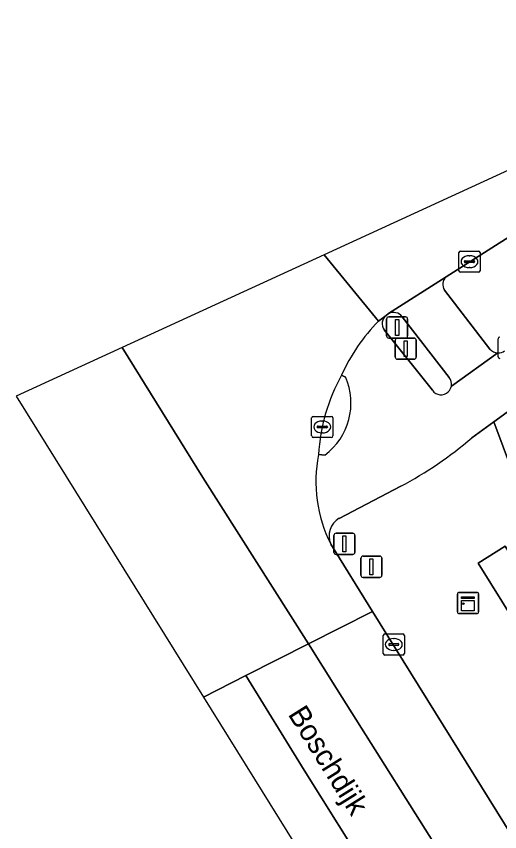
# Model space of a CAD drawing. Extents: x 160806 to 161707, y 383696 to 384148.
# Drawn here: x 160892.89 to 160915.71, y 383917.51 to 383955.96 of the extents above; entities that cross this region are included whole.
import ezdxf

# ---------------------------------------------------------------- set-up
doc = ezdxf.new("R2010")
doc.units = 0
for name, color, linetype in [('IMGEO_Drukknoppaal', 7, 'Continuous'), ('IMGEO_Fietspad_open', 7, 'Continuous'), ('IMGEO_Groenvoorziening', 7, 'Continuous'), ('IMGEO_Haag', 7, 'Continuous'), ('IMGEO_Kast', 7, 'Continuous'), ('IMGEO_Kolk', 7, 'Continuous'), ('IMGEO_Lichtmast', 7, 'Continuous'), ('IMGEO_Openbare_ruimte_label', 7, 'Continuous'), ('IMGEO_Rijbaan_lokaal_gesloten', 7, 'Continuous'), ('IMGEO_Rijbaan_lokaal_open', 7, 'Continuous'), ('IMGEO_Verkeerseiland_gesloten', 7, 'Continuous'), ('IMGEO_Verkeerseiland_groen', 7, 'Continuous'), ('IMGEO_Verkeerseiland_open', 7, 'Continuous'), ('IMGEO_Verkeersregelinstallatiepaal', 7, 'Continuous'), ('IMGEO_Voetpad_open', 7, 'Continuous')]:
    doc.layers.add(name, color=color, linetype=linetype)

msp = doc.modelspace()

# ---------------------------------------------------------------- linework, layer by layer
at = {"layer": 'IMGEO_Drukknoppaal'}
for p, q in [((160910.376, 383940.887), (160910.376, 383941.687)), ((160910.376, 383941.687), (160910.376, 383940.887)), ((160910.476, 383941.787), (160911.266, 383941.787)), ((160911.266, 383941.787), (160910.476, 383941.787)), ((160911.366, 383941.687), (160911.366, 383940.887)), ((160911.366, 383940.887), (160911.366, 383941.687)), ((160911.266, 383940.787), (160910.476, 383940.787)), ((160910.476, 383940.787), (160911.266, 383940.787))]:
    msp.add_line(p, q, dxfattribs=at)
msp.add_lwpolyline([(160910.796, 383941.662), (160910.946, 383941.662), (160910.946, 383940.912), (160910.796, 383940.912), (160910.796, 383941.662)], dxfattribs=at)
for centre, start, end in [((160910.476, 383941.687), 90, 180), ((160910.476, 383941.687), 90, 180), ((160911.266, 383941.687), 0, 90), ((160911.266, 383941.687), 360, 90), ((160910.476, 383940.887), 180, 270), ((160910.476, 383940.887), 180, 270), ((160911.266, 383940.887), 270, 0), ((160911.266, 383940.887), 270, 0)]:
    msp.add_arc(centre, 0.1, start, end, dxfattribs=at)
at = {"layer": 'IMGEO_Fietspad_open'}
for points in [[(160914.394, 383936.084), (160915.435, 383936.839), (160928.691, 383946.466), (160930.868, 383948.143)], [(160910.348, 383941.857), (160909.99, 383941.586)], [(160912.535, 383938.326), (160910.264, 383941.18)], [(160915.627, 383940.088), (160913.432, 383938.517)], [(160908.246, 383939.039), (160908.436, 383938.952)], [(160907.466, 383935.27), (160907.157, 383935.291)], [(160908.137, 383932.288), (160911.047, 383933.797)]]:
    msp.add_lwpolyline(points, dxfattribs=at)
for centre, radius, start, end in [((160910.656, 383941.475), 0.491, 128.8757, 216.9784), ((160916.234, 383935.44), 8.761, 135.4529, 155.7461), ((160915.641, 383940.616), 0.528, 268.4309, 304.9344), ((160905.618, 383937.726), 3.073, 306.9626, 23.5196), ((160912.945, 383938.61), 0.495, 313.4444, 349.2145), ((160912.943, 383938.609), 0.497, 214.7488, 313.6941), ((160902.215, 383950.316), 18.732, 298.1328, 310.5567), ((160913.674, 383934.037), 6.637, 169.108, 206.5048), ((160908.632, 383931.451), 0.973, 120.6113, 202.7173)]:
    msp.add_arc(centre, radius, start, end, dxfattribs=at)
at = {"layer": 'IMGEO_Groenvoorziening'}
msp.add_lwpolyline([(160916.408, 383927.422), (160917.684, 383928.212), (160915.977, 383930.968), (160914.701, 383930.178)], close=True, dxfattribs=at)
at = {"layer": 'IMGEO_Haag'}
msp.add_lwpolyline([(160916.408, 383927.422), (160917.684, 383928.212), (160915.977, 383930.968), (160914.701, 383930.178)], close=True, dxfattribs=at)
at = {"layer": 'IMGEO_Kast'}
for p, q in [((160913.79, 383928.797), (160914.631, 383928.797)), ((160914.631, 383928.797), (160913.79, 383928.797)), ((160914.715, 383928.722), (160914.715, 383927.881)), ((160914.715, 383927.881), (160914.715, 383928.722)), ((160913.715, 383927.872), (160913.715, 383928.713)), ((160913.715, 383928.713), (160913.715, 383927.872)), ((160914.64, 383927.797), (160913.799, 383927.797)), ((160913.799, 383927.797), (160914.64, 383927.797))]:
    msp.add_line(p, q, dxfattribs=at)
for points in [[(160913.91, 383928.587), (160914.51, 383928.587), (160914.51, 383928.502), (160913.91, 383928.502), (160913.91, 383928.587)], [(160913.91, 383928.412), (160914.51, 383928.412), (160914.51, 383927.923), (160913.91, 383927.923), (160913.91, 383928.412)]]:
    msp.add_lwpolyline(points, dxfattribs=at)
msp.add_circle((160913.994, 383928.261), 0.0377, dxfattribs=at)
for centre, start, end in [((160913.793, 383928.719), 92.4484, 184.2845), ((160913.793, 383928.719), 92.4484, 184.2845), ((160914.637, 383928.719), 2.4484, 94.2845), ((160914.637, 383928.719), 2.4484, 94.2845), ((160913.793, 383927.875), 182.4484, 274.2845), ((160913.793, 383927.875), 182.4484, 274.2845), ((160914.637, 383927.875), 272.4484, 4.2845), ((160914.637, 383927.875), 272.4484, 4.2845)]:
    msp.add_arc(centre, 0.0779, start, end, dxfattribs=at)
at = {"layer": 'IMGEO_Kolk'}
for p, q in [((160913.86, 383944.892), (160914.712, 383944.892)), ((160913.785, 383943.966), (160913.785, 383944.818)), ((160914.273, 383944.672), (160914.298, 383944.672)), ((160914.786, 383944.818), (160914.786, 383943.966)), ((160914.044, 383944.386), (160914.044, 383944.398)), ((160914.482, 383944.349), (160914.084, 383944.349)), ((160914.087, 383944.435), (160914.485, 383944.435)), ((160914.296, 383944.112), (160914.271, 383944.112)), ((160914.528, 383944.398), (160914.528, 383944.386)), ((160914.712, 383943.892), (160913.86, 383943.892)), ((160915.637, 383939.904), (160915.637, 383940.756)), ((160906.836, 383936.171), (160906.836, 383937.023)), ((160906.911, 383937.097), (160907.763, 383937.097)), ((160907.324, 383936.877), (160907.349, 383936.877)), ((160907.837, 383937.023), (160907.837, 383936.171)), ((160907.095, 383936.591), (160907.095, 383936.603)), ((160907.533, 383936.554), (160907.135, 383936.554)), ((160907.138, 383936.64), (160907.536, 383936.64)), ((160907.579, 383936.603), (160907.579, 383936.591)), ((160907.763, 383936.097), (160906.911, 383936.097)), ((160907.347, 383936.317), (160907.322, 383936.317)), ((160910.287, 383926.84), (160911.139, 383926.84)), ((160910.212, 383925.914), (160910.212, 383926.766)), ((160910.7, 383926.62), (160910.725, 383926.62)), ((160911.213, 383926.766), (160911.213, 383925.914)), ((160910.471, 383926.334), (160910.471, 383926.346)), ((160910.909, 383926.297), (160910.511, 383926.297)), ((160910.514, 383926.383), (160910.912, 383926.383)), ((160910.723, 383926.06), (160910.698, 383926.06)), ((160910.955, 383926.346), (160910.955, 383926.334)), ((160911.139, 383925.84), (160910.287, 383925.84))]:
    msp.add_line(p, q, dxfattribs=at)
for points in [[(160913.86, 383944.892), (160914.712, 383944.892)], [(160913.785, 383943.966), (160913.785, 383944.818)], [(160914.786, 383944.818), (160914.786, 383943.966)], [(160914.712, 383943.892), (160913.86, 383943.892)], [(160915.637, 383939.904), (160915.637, 383940.756)], [(160906.836, 383936.171), (160906.836, 383937.023)], [(160906.911, 383937.097), (160907.763, 383937.097)], [(160907.837, 383937.023), (160907.837, 383936.171)], [(160907.763, 383936.097), (160906.911, 383936.097)], [(160910.287, 383926.84), (160911.139, 383926.84)], [(160910.212, 383925.914), (160910.212, 383926.766)], [(160911.213, 383926.766), (160911.213, 383925.914)], [(160911.139, 383925.84), (160910.287, 383925.84)]]:
    msp.add_lwpolyline(points, dxfattribs=at)
for centre, radius, start, end in [((160913.862, 383944.816), 0.0765, 91.552, 178.448), ((160913.862, 383944.816), 0.0765, 91.552, 178.448), ((160914.71, 383944.816), 0.0765, 1.552, 88.448), ((160914.71, 383944.816), 0.0765, 1.552, 88.448), ((160914.084, 383944.395), 0.0403, 85.8775, 175.7526), ((160914.081, 383944.385), 0.0366, 178.938, 274.7102), ((160914.485, 383944.392), 0.043, 264.8664, 352.4533), ((160914.489, 383944.397), 0.0386, 1.7309, 96.639), ((160913.862, 383943.968), 0.0765, 181.552, 268.448), ((160913.862, 383943.968), 0.0765, 181.552, 268.448), ((160914.71, 383943.968), 0.0765, 271.552, 358.448), ((160914.71, 383943.968), 0.0765, 271.552, 358.448), ((160915.714, 383940.754), 0.0765, 91.552, 178.448), ((160915.714, 383940.754), 0.0765, 91.552, 178.448), ((160915.714, 383939.906), 0.0765, 181.552, 268.448), ((160915.714, 383939.906), 0.0765, 181.552, 268.448), ((160906.913, 383937.021), 0.0765, 91.552, 178.448), ((160906.913, 383937.021), 0.0765, 91.552, 178.448), ((160907.761, 383937.021), 0.0765, 1.552, 88.448), ((160907.761, 383937.021), 0.0765, 1.552, 88.448), ((160907.135, 383936.6), 0.0403, 85.8775, 175.7526), ((160907.132, 383936.59), 0.0366, 178.938, 274.7102), ((160907.536, 383936.597), 0.043, 264.8664, 352.4533), ((160907.54, 383936.602), 0.0386, 1.7309, 96.639), ((160906.913, 383936.173), 0.0765, 181.552, 268.448), ((160906.913, 383936.173), 0.0765, 181.552, 268.448), ((160907.761, 383936.173), 0.0765, 271.552, 358.448), ((160907.761, 383936.173), 0.0765, 271.552, 358.448), ((160910.289, 383926.764), 0.0765, 91.552, 178.448), ((160910.289, 383926.764), 0.0765, 91.552, 178.448), ((160911.137, 383926.764), 0.0765, 1.552, 88.448), ((160911.137, 383926.764), 0.0765, 1.552, 88.448), ((160910.511, 383926.343), 0.0403, 85.8775, 175.7526), ((160910.508, 383926.333), 0.0366, 178.938, 274.7102), ((160910.912, 383926.34), 0.043, 264.8664, 352.4533), ((160910.916, 383926.345), 0.0386, 1.7309, 96.639), ((160910.289, 383925.916), 0.0765, 181.552, 268.448), ((160910.289, 383925.916), 0.0765, 181.552, 268.448), ((160911.137, 383925.916), 0.0765, 271.552, 358.448), ((160911.137, 383925.916), 0.0765, 271.552, 358.448)]:
    msp.add_arc(centre, radius, start, end, dxfattribs=at)
for centre, major_axis, ratio, start_param, end_param in [((160914.272, 383944.392), (-0.387, 0.002), 0.722429, 4.712389, 7.853982), ((160914.297, 383944.392), (-0.39, 0.002), 0.717154, 1.570796, 4.712389), ((160907.323, 383936.597), (-0.387, 0.002), 0.722429, 4.712389, 7.853982), ((160907.348, 383936.597), (-0.39, 0.002), 0.717154, 1.570796, 4.712389), ((160910.699, 383926.34), (-0.387, 0.002), 0.722429, 4.712389, 7.853982), ((160910.724, 383926.34), (-0.39, 0.002), 0.717154, 1.570796, 4.712389)]:
    msp.add_ellipse(centre, major_axis=major_axis, ratio=ratio, start_param=start_param, end_param=end_param, dxfattribs=at)
at = {"layer": 'IMGEO_Lichtmast'}
for p, q in [((160907.885, 383930.684), (160907.885, 383931.484)), ((160907.885, 383931.484), (160907.885, 383930.684)), ((160907.985, 383931.584), (160908.775, 383931.584)), ((160908.775, 383931.584), (160907.985, 383931.584)), ((160908.875, 383931.484), (160908.875, 383930.684)), ((160908.875, 383930.684), (160908.875, 383931.484)), ((160908.775, 383930.584), (160907.985, 383930.584)), ((160907.985, 383930.584), (160908.775, 383930.584))]:
    msp.add_line(p, q, dxfattribs=at)
msp.add_lwpolyline([(160908.305, 383931.459), (160908.455, 383931.459), (160908.455, 383930.709), (160908.305, 383930.709), (160908.305, 383931.459)], dxfattribs=at)
for centre, start, end in [((160907.985, 383931.484), 90, 180), ((160907.985, 383931.484), 90, 180), ((160908.775, 383931.484), 0, 90), ((160908.775, 383931.484), 360, 90), ((160907.985, 383930.684), 180, 270), ((160907.985, 383930.684), 180, 270), ((160908.775, 383930.684), 270, 0), ((160908.775, 383930.684), 270, 0)]:
    msp.add_arc(centre, 0.1, start, end, dxfattribs=at)
at = {"layer": 'IMGEO_Rijbaan_lokaal_gesloten'}
for points in [[(160909.99, 383941.586), (160907.425, 383944.713), (160897.886, 383940.336)], [(160897.886, 383940.336), (160892.895, 383938.045), (160901.725, 383923.859), (160903.723, 383924.87), (160906.682, 383926.368), (160901.707, 383934.21), (160897.886, 383940.336)], [(160897.886, 383940.336), (160901.707, 383934.21), (160906.682, 383926.368), (160909.71, 383927.9), (160907.735, 383931.075)], [(160909.71, 383927.9), (160906.682, 383926.368), (160908.015, 383924.267), (160913.566, 383915.455), (160925.814, 383895.944), (160938.564, 383875.623), (160945.002, 383865.641)], [(160936.803, 383883.721), (160935.997, 383885.302), (160935.062, 383887.143), (160909.71, 383927.9)], [(160949.144, 383858.905), (160948.516, 383859.997), (160945.002, 383865.641), (160938.564, 383875.623), (160925.814, 383895.944), (160913.566, 383915.455), (160908.015, 383924.267), (160906.682, 383926.368), (160903.723, 383924.87), (160906.479, 383920.419), (160912.866, 383910.221), (160927.745, 383886.505), (160950.252, 383850.619), (160952.745, 383846.411), (160954.11, 383843.892), (160955.019, 383841.251), (160955.876, 383837.546), (160955.934, 383835.901), (160961.513, 383837.987), (160963.214, 383838.795)], [(160954.311, 383835.295), (160955.934, 383835.901), (160955.876, 383837.546), (160955.019, 383841.251), (160954.11, 383843.892), (160952.745, 383846.411), (160950.252, 383850.619), (160927.745, 383886.505), (160912.866, 383910.221), (160906.479, 383920.419), (160903.723, 383924.87), (160901.725, 383923.859), (160952.654, 383842.04), (160954.311, 383835.295)]]:
    msp.add_lwpolyline(points, dxfattribs=at)
for centre, radius, start, end in [((160916.234, 383935.44), 8.761, 135.4529, 155.7461), ((160916.102, 383934.724), 8.963, 151.2222, 176.3749), ((160913.674, 383934.037), 6.637, 169.108, 206.5048)]:
    msp.add_arc(centre, radius, start, end, dxfattribs=at)
at = {"layer": 'IMGEO_Rijbaan_lokaal_open'}
for points in [[(161008.487, 383991.097), (160907.425, 383944.713)], [(160907.425, 383944.713), (160909.99, 383941.586), (160910.348, 383941.857), (160910.466, 383941.945), (160913.178, 383943.681), (160916.333, 383945.674), (160930.784, 383954.763), (160931.961, 383955.496), (160937.776, 383958.172), (160945.199, 383961.672), (160948.108, 383963.03), (160966.644, 383971.527)]]:
    msp.add_lwpolyline(points, dxfattribs=at)
at = {"layer": 'IMGEO_Verkeerseiland_gesloten'}
for points in [[(160910.466, 383941.945), (160910.348, 383941.857)], [(160913.323, 383938.932), (160911.109, 383941.796)], [(160910.264, 383941.18), (160912.535, 383938.326)]]:
    msp.add_lwpolyline(points, dxfattribs=at)
for centre, radius, start, end in [((160910.656, 383941.475), 0.491, 128.8757, 216.9784), ((160910.694, 383941.468), 0.529, 38.351, 115.5556), ((160912.948, 383938.612), 0.493, 348.9258, 40.507), ((160912.945, 383938.61), 0.495, 313.4444, 349.2145), ((160912.943, 383938.609), 0.497, 214.7488, 313.6941)]:
    msp.add_arc(centre, radius, start, end, dxfattribs=at)
at = {"layer": 'IMGEO_Verkeerseiland_groen'}
for points in [[(160916.333, 383945.674), (160913.178, 383943.681)], [(160913.107, 383943.045), (160915.249, 383940.272)]]:
    msp.add_lwpolyline(points, dxfattribs=at)
for centre, radius, start, end in [((160913.527, 383943.32), 0.502, 134.0183, 213.242), ((160915.647, 383940.609), 0.521, 220.2524, 267.8365), ((160915.641, 383940.616), 0.528, 268.4309, 304.9344)]:
    msp.add_arc(centre, radius, start, end, dxfattribs=at)
at = {"layer": 'IMGEO_Verkeerseiland_open'}
for points in [[(160908.436, 383938.952), (160908.246, 383939.039)], [(160907.157, 383935.291), (160907.466, 383935.27)]]:
    msp.add_lwpolyline(points, dxfattribs=at)
for centre, radius, start, end in [((160916.102, 383934.724), 8.963, 151.2222, 176.3749), ((160905.618, 383937.726), 3.073, 306.9626, 23.5196)]:
    msp.add_arc(centre, radius, start, end, dxfattribs=at)
at = {"layer": 'IMGEO_Verkeersregelinstallatiepaal'}
for p, q in [((160910.781, 383939.889), (160910.781, 383940.689)), ((160910.781, 383940.689), (160910.781, 383939.889)), ((160910.881, 383940.789), (160911.671, 383940.789)), ((160911.671, 383940.789), (160910.881, 383940.789)), ((160911.771, 383940.689), (160911.771, 383939.889)), ((160911.771, 383939.889), (160911.771, 383940.689)), ((160911.671, 383939.789), (160910.881, 383939.789)), ((160910.881, 383939.789), (160911.671, 383939.789)), ((160909.161, 383929.605), (160909.161, 383930.405)), ((160909.161, 383930.405), (160909.161, 383929.605)), ((160909.261, 383930.505), (160910.051, 383930.505)), ((160910.051, 383930.505), (160909.261, 383930.505)), ((160910.151, 383930.405), (160910.151, 383929.605)), ((160910.151, 383929.605), (160910.151, 383930.405)), ((160910.051, 383929.505), (160909.261, 383929.505)), ((160909.261, 383929.505), (160910.051, 383929.505))]:
    msp.add_line(p, q, dxfattribs=at)
for points in [[(160911.201, 383940.664), (160911.351, 383940.664), (160911.351, 383939.914), (160911.201, 383939.914), (160911.201, 383940.664)], [(160909.581, 383930.38), (160909.731, 383930.38), (160909.731, 383929.63), (160909.581, 383929.63), (160909.581, 383930.38)]]:
    msp.add_lwpolyline(points, dxfattribs=at)
for centre, start, end in [((160910.881, 383940.689), 90, 180), ((160910.881, 383940.689), 90, 180), ((160911.671, 383940.689), 0, 90), ((160911.671, 383940.689), 360, 90), ((160910.881, 383939.889), 180, 270), ((160910.881, 383939.889), 180, 270), ((160911.671, 383939.889), 270, 0), ((160911.671, 383939.889), 270, 0), ((160909.261, 383930.405), 90, 180), ((160909.261, 383930.405), 90, 180), ((160910.051, 383930.405), 0, 90), ((160910.051, 383930.405), 360, 90), ((160909.261, 383929.605), 180, 270), ((160909.261, 383929.605), 180, 270), ((160910.051, 383929.605), 270, 0), ((160910.051, 383929.605), 270, 0)]:
    msp.add_arc(centre, 0.1, start, end, dxfattribs=at)
at = {"layer": 'IMGEO_Voetpad_open'}
for points in [[(160930.868, 383948.143), (160928.691, 383946.466), (160915.435, 383936.839), (160917.241, 383931.994), (160917.656, 383932.175), (160917.798, 383931.792), (160919.628, 383932.473), (160919.501, 383932.83), (160920.227, 383933.101), (160919.857, 383934.55), (160919.885, 383935.916), (160932.177, 383945.058), (160934.167, 383946.323), (160938.381, 383949.591), (160940.209, 383950.755), (160941.963, 383951.859), (160947.428, 383954.476), (160947.637, 383954.018), (160948.491, 383954.34), (160961.285, 383959.048), (160961.058, 383959.607), (160959.525, 383959.063)], [(160913.178, 383943.681), (160910.466, 383941.945)], [(160915.249, 383940.272), (160913.107, 383943.045)], [(160911.109, 383941.796), (160913.323, 383938.932)], [(160913.432, 383938.517), (160915.627, 383940.088)], [(160917.241, 383931.994), (160915.435, 383936.839), (160914.394, 383936.084)], [(160911.047, 383933.797), (160908.137, 383932.288)], [(160907.735, 383931.075), (160909.71, 383927.9), (160935.062, 383887.143), (160935.997, 383885.302), (160936.803, 383883.721)]]:
    msp.add_lwpolyline(points, dxfattribs=at)
msp.add_lwpolyline([(160914.701, 383930.178), (160915.977, 383930.968), (160917.684, 383928.212), (160916.408, 383927.422)], close=True, dxfattribs=at)
for centre, radius, start, end in [((160913.527, 383943.32), 0.502, 134.0183, 213.242), ((160910.694, 383941.468), 0.529, 38.351, 115.5556), ((160915.647, 383940.609), 0.521, 220.2524, 267.8365), ((160912.948, 383938.612), 0.493, 348.9258, 40.507), ((160902.215, 383950.316), 18.732, 298.1328, 310.5567), ((160908.632, 383931.451), 0.973, 120.6113, 202.7173)]:
    msp.add_arc(centre, radius, start, end, dxfattribs=at)

# ---------------------------------------------------------------- texts
at = {"layer": 'IMGEO_Openbare_ruimte_label'}
msp.add_text('Boschdijk', height=1, rotation=302.0054, dxfattribs=at).set_placement((160905.692, 383923.051))

doc.saveas('drawing.dxf')
